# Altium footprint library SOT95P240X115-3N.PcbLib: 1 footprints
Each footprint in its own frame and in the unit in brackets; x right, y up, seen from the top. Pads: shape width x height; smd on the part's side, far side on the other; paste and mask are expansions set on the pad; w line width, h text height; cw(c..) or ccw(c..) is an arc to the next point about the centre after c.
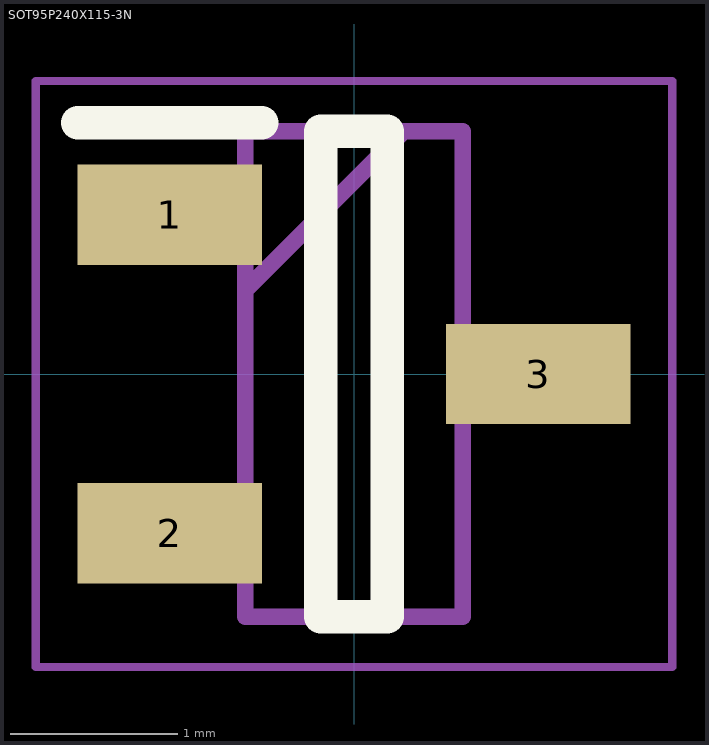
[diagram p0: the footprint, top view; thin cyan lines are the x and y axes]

## SOT95P240X115-3N [mm]
pads (3):
  rect 1.1x0.6 smd: 1(-1.1,0.95) 2(-1.1,-0.95) 3(1.1,0)
Top Overlay:
  lines w0.2: -1.65,1.5 -0.55,1.5 ; -0.2,-1.45 0.2,-1.45 0.2,1.45 -0.2,1.45 -0.2,-1.45
Mechanical 15:
  lines w0.1: -0.65,0.5 0.3,1.45 ; -0.65,-1.45 0.65,-1.45 0.65,1.45 -0.65,1.45 -0.65,-1.45
Mechanical 20:
  lines w0.05: -1.9,-1.75 1.9,-1.75 1.9,1.75 -1.9,1.75 -1.9,-1.75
